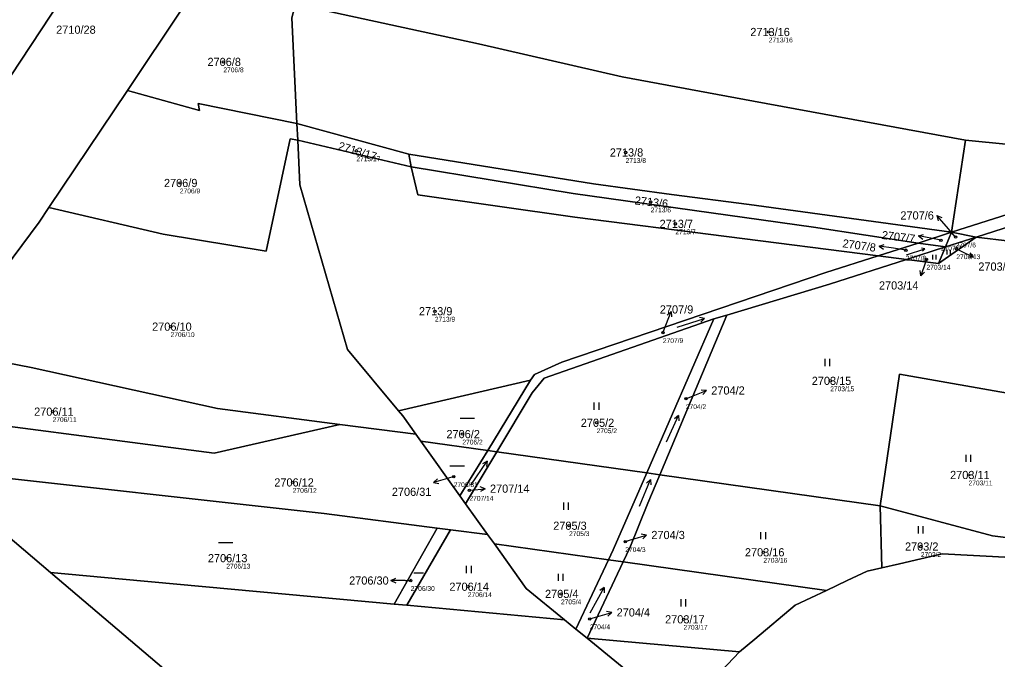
# Model space of a CAD drawing. Extents: x -739214 to -733252, y -1147612 to -1142842.
# Drawn here: x -738144.3 to -737941, y -1146269.3 to -1146136.2 of the extents above; entities that cross this region are included whole.
import ezdxf

# ---------------------------------------------------------------- set-up
doc = ezdxf.new("R2010")
doc.units = 0
for name, color, linetype in [('Definiční body', 7, 'Continuous'), ('Hranice parcel', 7, 'Continuous'), ('Parcelní čísla', 7, 'Continuous'), ('Polygon parcely', 7, 'Continuous'), ('Pop  PČ popisy', 7, 'Continuous'), ('Značky kultur', 7, 'Continuous')]:
    doc.layers.add(name, color=color, linetype=linetype)

msp = doc.modelspace()

# ---------------------------------------------------------------- linework, layer by layer
at = {"layer": 'Definiční body'}
for centre in [(-737988.53, -1146138.76), (-738101.92, -1146144.98), (-738074.27, -1146163.48), (-738018.28, -1146163.82), (-738110.96, -1146170.16), (-738013.08, -1146174.11), (-738007.93, -1146178.66), (-737952.75, -1146182.07), (-737949.69, -1146181.41), (-737960.03, -1146184.14), (-737949.52, -1146183.84), (-737955.74, -1146186.02), (-738057.95, -1146196.83), (-738112.89, -1146200.04), (-738010.54, -1146201.3), (-737975.75, -1146211.31), (-738005.76, -1146215.03), (-738137.42, -1146217.72), (-738024.31, -1146220.03), (-738052.23, -1146222.39), (-738054.03, -1146231.24), (-737946.99, -1146230.89), (-738087.49, -1146232.44), (-738050.76, -1146234.09), (-738030.04, -1146241.44), (-738018.36, -1146244.75), (-737956.91, -1146245.77), (-737989.65, -1146246.97), (-738101.3, -1146248.19), (-738062.96, -1146252.84), (-738051.09, -1146254.13), (-738031.73, -1146255.62), (-738025.74, -1146260.82), (-738006.24, -1146260.91)]:
    msp.add_circle(centre, 0.25, dxfattribs=at)
at = {"layer": 'Hranice parcel'}
for p, q in [((-738110.44, -1146133.83), (-738121.87, -1146150.92)), ((-738121.87, -1146150.92), (-738138.18, -1146175.28)), ((-738086.46, -1146161.25), (-738086.63, -1146157.8)), ((-738086.63, -1146157.8), (-738063.36, -1146164.2)), ((-738086.02, -1146170.57), (-738086.46, -1146161.25)), ((-738062.9, -1146166.81), (-738086.46, -1146161.25)), ((-737947.62, -1146161.29), (-737950.55, -1146180.42)), ((-737909.21, -1146165.1), (-737947.62, -1146161.29)), ((-738063.36, -1146164.2), (-738062.9, -1146166.81)), ((-738076.11, -1146204.78), (-738086.02, -1146170.57)), ((-737950.55, -1146180.42), (-737957.5, -1146182.65)), ((-737950.55, -1146180.42), (-737951.8, -1146183.47)), ((-737950.55, -1146180.42), (-737945.43, -1146181.43)), ((-737957.5, -1146182.65), (-737965.76, -1146185.31)), ((-737957.5, -1146182.65), (-737951.8, -1146183.47)), ((-737953.21, -1146186.91), (-737945.43, -1146181.43)), ((-737945.43, -1146181.43), (-737951.8, -1146183.47)), ((-737951.8, -1146183.47), (-737959.87, -1146186.06)), ((-737951.8, -1146183.47), (-737953.21, -1146186.91)), ((-737965.76, -1146185.31), (-737959.87, -1146186.06)), ((-737959.87, -1146186.06), (-737953.21, -1146186.91)), ((-737999.95, -1146198.39), (-738013.91, -1146230.45)), ((-738011.17, -1146230.84), (-737997.23, -1146197.63)), ((-737997.23, -1146197.63), (-737999.95, -1146198.39)), ((-738065.51, -1146217.55), (-738076.11, -1146204.78)), ((-738038.05, -1146211.17), (-738065.51, -1146217.55)), ((-738046.97, -1146225.8), (-738038.05, -1146211.17)), ((-738077.68, -1146220.38), (-738061.9, -1146222.43)), ((-738061.9, -1146222.43), (-738060.89, -1146223.85)), ((-738060.89, -1146223.85), (-738046.97, -1146225.8)), ((-738052.73, -1146235.25), (-738060.89, -1146223.85)), ((-738052.73, -1146235.25), (-738046.97, -1146225.8)), ((-738045.07, -1146226.07), (-738051.56, -1146236.89)), ((-738046.97, -1146225.8), (-738045.07, -1146226.07)), ((-738045.07, -1146226.07), (-738013.91, -1146230.45)), ((-738013.91, -1146230.45), (-738011.17, -1146230.84)), ((-738011.17, -1146230.84), (-737965.37, -1146237.28)), ((-738051.56, -1146236.89), (-738052.73, -1146235.25)), ((-738046.98, -1146243.28), (-738051.56, -1146236.89)), ((-737965.37, -1146237.28), (-737965, -1146250.2)), ((-738066.44, -1146257.74), (-738057.45, -1146241.93)), ((-738054.72, -1146242.29), (-738063.79, -1146257.98)), ((-738057.45, -1146241.93), (-738054.72, -1146242.29)), ((-738054.72, -1146242.29), (-738046.98, -1146243.28)), ((-738045.58, -1146245.23), (-738046.98, -1146243.28)), ((-738045.58, -1146245.23), (-738021.87, -1146248.55)), ((-738038.95, -1146254.51), (-738045.58, -1146245.23)), ((-738021.87, -1146248.55), (-738028.62, -1146262.95)), ((-738018.77, -1146248.98), (-738026.3, -1146264.85)), ((-738021.87, -1146248.55), (-738018.77, -1146248.98)), ((-738018.77, -1146248.98), (-737976.52, -1146254.9)), ((-737965, -1146250.2), (-737961.38, -1146249.36)), ((-737972.22, -1146252.87), (-737968.07, -1146250.91)), ((-737968.07, -1146250.91), (-737965, -1146250.2)), ((-737976.52, -1146254.9), (-737972.22, -1146252.87)), ((-738031.02, -1146260.99), (-738038.95, -1146254.51)), ((-737983.04, -1146257.99), (-737976.52, -1146254.9)), ((-738066.44, -1146257.74), (-738063.79, -1146257.98)), ((-738063.79, -1146257.98), (-738031.02, -1146260.99)), ((-738031.02, -1146260.99), (-738028.62, -1146262.95)), ((-738028.62, -1146262.95), (-738026.3, -1146264.85)), ((-738026.3, -1146264.85), (-737994.62, -1146267.7))]:
    msp.add_line(p, q, dxfattribs=at)
for points in [[(-738133.65, -1146128.9), (-738146.1, -1146147.9), (-738187.24, -1146201.43)], [(-738086.63, -1146157.8), (-738087.67, -1146135.8), (-738086.89, -1146132.94)], [(-737947.62, -1146161.29), (-737991.69, -1146153.16), (-738018.99, -1146148.09), (-738048.91, -1146141.19), (-738086.89, -1146132.94)], [(-738121.87, -1146150.92), (-738106.86, -1146155.08), (-738107.17, -1146153.63), (-738086.63, -1146157.8)], [(-738138.18, -1146175.28), (-738114.43, -1146180.81), (-738093.03, -1146184.32), (-738088.06, -1146160.96), (-738086.46, -1146161.25)], [(-737950.55, -1146180.42), (-737992.57, -1146174.67), (-738008.72, -1146172.55), (-738025, -1146170.34), (-738063.36, -1146164.2)], [(-737950.55, -1146180.42), (-737938.79, -1146176.64), (-737921.97, -1146170.82), (-737909.21, -1146165.1)], [(-738062.9, -1146166.81), (-738029.2, -1146172.33), (-737979.26, -1146179.33), (-737957.5, -1146182.65)], [(-738062.9, -1146166.81), (-738061.52, -1146172.64), (-738028.84, -1146177.24), (-737965.76, -1146185.31)], [(-737913.09, -1146169.9), (-737921.19, -1146173.66), (-737945.43, -1146181.43)], [(-738138.18, -1146175.28), (-738140.2, -1146178.3), (-738160.12, -1146204.97)], [(-737945.43, -1146181.43), (-737938.44, -1146182.28), (-737917.93, -1146184.94)], [(-737965.76, -1146185.31), (-737976.67, -1146188.81), (-738031.53, -1146207.43), (-738037.23, -1146209.99), (-738038.05, -1146211.17)], [(-737959.87, -1146186.06), (-737975.87, -1146191.19), (-737997.23, -1146197.63)], [(-737999.95, -1146198.39), (-738035.25, -1146210.77), (-738037.71, -1146213.81), (-738045.07, -1146226.07)], [(-738160.12, -1146204.97), (-738141.87, -1146208.53), (-738103.15, -1146217.07), (-738077.68, -1146220.38)], [(-737927.86, -1146215.8), (-737961.35, -1146209.95), (-737965.37, -1146237.28)], [(-738169.69, -1146217.79), (-738103.82, -1146226.35), (-738077.68, -1146220.38)], [(-738065.51, -1146217.55), (-738064.64, -1146218.6), (-738061.9, -1146222.43)], [(-738163.37, -1146229.62), (-738158.27, -1146230.29), (-738080.93, -1146238.92), (-738057.45, -1146241.93)], [(-738163.37, -1146229.62), (-738161.77, -1146230.87), (-738137.88, -1146251.17)], [(-738013.91, -1146230.45), (-738020.89, -1146246.47), (-738021.87, -1146248.55)], [(-738011.17, -1146230.84), (-738013.65, -1146236.75), (-738017.39, -1146246.07), (-738018.77, -1146248.98)], [(-737936.96, -1146244.2), (-737942.04, -1146243.53), (-737965.37, -1146237.28)], [(-737961.38, -1146249.36), (-737952.48, -1146247.3), (-737938.13, -1146248.08)], [(-738137.88, -1146251.17), (-738122.88, -1146252.56), (-738066.44, -1146257.74)], [(-738137.88, -1146251.17), (-738110.15, -1146274.73), (-738101.44, -1146281.71), (-738091.06, -1146290.01)], [(-737994.62, -1146267.7), (-737991.42, -1146265.02), (-737983.04, -1146257.99)], [(-737994.62, -1146267.7), (-738005.71, -1146279.42), (-738008.28, -1146279.57), (-738026.3, -1146264.85)]]:
    msp.add_lwpolyline(points, dxfattribs=at)
at = {"layer": 'Polygon parcely'}
for points in [[(-738071.28, -1146096.04), (-738082.64, -1146117.38), (-738086.89, -1146132.94), (-738048.91, -1146141.19), (-738018.99, -1146148.09), (-737991.69, -1146153.16), (-737947.62, -1146161.29), (-737909.21, -1146165.1), (-737907.13, -1146162.96), (-737889.89, -1146129.54), (-737952.88, -1146119.6), (-738034.62, -1146103.8)], [(-738205.06, -1146197.26), (-738187.24, -1146201.43), (-738146.1, -1146147.9), (-738133.65, -1146128.9), (-738131.34, -1146125.38), (-738147.44, -1146119.09), (-738158.29, -1146135.07), (-738163.2, -1146140.38), (-738171.83, -1146149.73), (-738181.3, -1146167.36), (-738188.43, -1146175.89), (-738195.24, -1146183.95), (-738201.39, -1146192.77)], [(-738187.24, -1146201.43), (-738193.9, -1146210.1), (-738201.84, -1146219.5), (-738199.97, -1146222.65), (-738198.89, -1146224.47), (-738196.13, -1146228.59), (-738179.3, -1146230.66), (-738173.26, -1146221.9), (-738169.69, -1146217.79), (-738160.12, -1146204.97), (-738140.2, -1146178.3), (-738138.18, -1146175.28), (-738121.87, -1146150.92), (-738110.44, -1146133.83), (-738126.38, -1146131.45), (-738133.65, -1146128.9), (-738146.1, -1146147.9)], [(-738107.17, -1146153.63), (-738086.63, -1146157.8), (-738087.67, -1146135.8), (-738086.89, -1146132.94), (-738107.97, -1146130.15), (-738110.44, -1146133.83), (-738121.87, -1146150.92), (-738106.86, -1146155.08)], [(-738018.99, -1146148.09), (-738048.91, -1146141.19), (-738086.89, -1146132.94), (-738087.67, -1146135.8), (-738086.63, -1146157.8), (-738063.36, -1146164.2), (-738025, -1146170.34), (-738008.72, -1146172.55), (-737992.57, -1146174.67), (-737950.55, -1146180.42), (-737947.62, -1146161.29), (-737991.69, -1146153.16)], [(-738088.06, -1146160.96), (-738086.46, -1146161.25), (-738086.63, -1146157.8), (-738107.17, -1146153.63), (-738106.86, -1146155.08), (-738121.87, -1146150.92), (-738138.18, -1146175.28), (-738114.43, -1146180.81), (-738093.03, -1146184.32)], [(-738086.63, -1146157.8), (-738086.46, -1146161.25), (-738062.9, -1146166.81), (-738063.36, -1146164.2)], [(-738086.02, -1146170.57), (-738086.46, -1146161.25), (-738088.06, -1146160.96), (-738093.03, -1146184.32), (-738114.43, -1146180.81), (-738138.18, -1146175.28), (-738140.2, -1146178.3), (-738160.12, -1146204.97), (-738141.87, -1146208.53), (-738103.15, -1146217.07), (-738077.68, -1146220.38), (-738061.9, -1146222.43), (-738064.64, -1146218.6), (-738065.51, -1146217.55), (-738076.11, -1146204.78)], [(-738062.9, -1146166.81), (-738086.46, -1146161.25), (-738086.02, -1146170.57), (-738076.11, -1146204.78), (-738065.51, -1146217.55), (-738038.05, -1146211.17), (-738037.23, -1146209.99), (-738031.53, -1146207.43), (-737976.67, -1146188.81), (-737965.76, -1146185.31), (-738028.84, -1146177.24), (-738061.52, -1146172.64)], [(-737950.55, -1146180.42), (-737938.79, -1146176.64), (-737921.97, -1146170.82), (-737909.21, -1146165.1), (-737947.62, -1146161.29)], [(-738063.36, -1146164.2), (-738062.9, -1146166.81), (-738029.2, -1146172.33), (-737979.26, -1146179.33), (-737957.5, -1146182.65), (-737950.55, -1146180.42), (-737992.57, -1146174.67), (-738008.72, -1146172.55), (-738025, -1146170.34)], [(-737950.55, -1146180.42), (-737945.43, -1146181.43), (-737921.19, -1146173.66), (-737913.09, -1146169.9), (-737910.33, -1146168.28), (-737907.35, -1146166.88), (-737906.08, -1146165.16), (-737909.21, -1146165.1), (-737921.97, -1146170.82), (-737938.79, -1146176.64)], [(-738061.52, -1146172.64), (-738028.84, -1146177.24), (-737965.76, -1146185.31), (-737957.5, -1146182.65), (-737979.26, -1146179.33), (-738029.2, -1146172.33), (-738062.9, -1146166.81)], [(-737945.43, -1146181.43), (-737938.44, -1146182.28), (-737917.93, -1146184.94), (-737913.09, -1146169.9), (-737921.19, -1146173.66)], [(-737957.5, -1146182.65), (-737951.8, -1146183.47), (-737950.55, -1146180.42)], [(-737950.55, -1146180.42), (-737951.8, -1146183.47), (-737945.43, -1146181.43)], [(-737997.23, -1146197.63), (-738011.17, -1146230.84), (-737965.37, -1146237.28), (-737961.35, -1146209.95), (-737927.86, -1146215.8), (-737917.93, -1146184.94), (-737938.44, -1146182.28), (-737945.43, -1146181.43), (-737953.21, -1146186.91), (-737959.87, -1146186.06), (-737975.87, -1146191.19)], [(-737965.76, -1146185.31), (-737959.87, -1146186.06), (-737951.8, -1146183.47), (-737957.5, -1146182.65)], [(-737945.43, -1146181.43), (-737951.8, -1146183.47), (-737953.21, -1146186.91)], [(-737959.87, -1146186.06), (-737953.21, -1146186.91), (-737951.8, -1146183.47)], [(-738031.53, -1146207.43), (-738037.23, -1146209.99), (-738038.05, -1146211.17), (-738046.97, -1146225.8), (-738045.07, -1146226.07), (-738037.71, -1146213.81), (-738035.25, -1146210.77), (-737999.95, -1146198.39), (-737997.23, -1146197.63), (-737975.87, -1146191.19), (-737959.87, -1146186.06), (-737965.76, -1146185.31), (-737976.67, -1146188.81)], [(-738037.71, -1146213.81), (-738045.07, -1146226.07), (-738013.91, -1146230.45), (-737999.95, -1146198.39), (-738035.25, -1146210.77)], [(-738013.91, -1146230.45), (-738011.17, -1146230.84), (-737997.23, -1146197.63), (-737999.95, -1146198.39)], [(-738160.12, -1146204.97), (-738169.69, -1146217.79), (-738103.82, -1146226.35), (-738077.68, -1146220.38), (-738103.15, -1146217.07), (-738141.87, -1146208.53)], [(-738060.89, -1146223.85), (-738046.97, -1146225.8), (-738038.05, -1146211.17), (-738065.51, -1146217.55), (-738064.64, -1146218.6), (-738061.9, -1146222.43)], [(-737965.37, -1146237.28), (-737942.04, -1146243.53), (-737936.96, -1146244.2), (-737936.45, -1146242.51), (-737927.86, -1146215.8), (-737961.35, -1146209.95)], [(-738046.98, -1146243.28), (-738051.56, -1146236.89), (-738052.73, -1146235.25), (-738060.89, -1146223.85), (-738061.9, -1146222.43), (-738077.68, -1146220.38), (-738103.82, -1146226.35), (-738169.69, -1146217.79), (-738173.26, -1146221.9), (-738172.94, -1146222.15), (-738163.37, -1146229.62), (-738158.27, -1146230.29), (-738080.93, -1146238.92), (-738057.45, -1146241.93), (-738054.72, -1146242.29)], [(-738099.06, -1146304.13), (-738091.06, -1146290.01), (-738101.44, -1146281.71), (-738110.15, -1146274.73), (-738137.88, -1146251.17), (-738161.77, -1146230.87), (-738163.37, -1146229.62), (-738172.94, -1146222.15), (-738173.26, -1146221.9), (-738179.3, -1146230.66), (-738187.36, -1146241.45), (-738173.43, -1146262.56), (-738160.45, -1146278.42), (-738140.73, -1146296.36), (-738128.52, -1146309.45), (-738121.57, -1146300.59), (-738103.8, -1146313.3)], [(-738052.73, -1146235.25), (-738046.97, -1146225.8), (-738060.89, -1146223.85)], [(-738052.73, -1146235.25), (-738051.56, -1146236.89), (-738045.07, -1146226.07), (-738046.97, -1146225.8)], [(-738021.87, -1146248.55), (-738020.89, -1146246.47), (-738013.91, -1146230.45), (-738045.07, -1146226.07), (-738051.56, -1146236.89), (-738046.98, -1146243.28), (-738045.58, -1146245.23)], [(-738066.44, -1146257.74), (-738057.45, -1146241.93), (-738080.93, -1146238.92), (-738158.27, -1146230.29), (-738163.37, -1146229.62), (-738161.77, -1146230.87), (-738137.88, -1146251.17), (-738122.88, -1146252.56)], [(-738020.89, -1146246.47), (-738021.87, -1146248.55), (-738018.77, -1146248.98), (-738017.39, -1146246.07), (-738013.65, -1146236.75), (-738011.17, -1146230.84), (-738013.91, -1146230.45)], [(-737968.07, -1146250.91), (-737965, -1146250.2), (-737965.37, -1146237.28), (-738011.17, -1146230.84), (-738013.65, -1146236.75), (-738017.39, -1146246.07), (-738018.77, -1146248.98), (-737976.52, -1146254.9), (-737972.22, -1146252.87)], [(-737965.37, -1146237.28), (-737965, -1146250.2), (-737961.38, -1146249.36), (-737952.48, -1146247.3), (-737938.13, -1146248.08), (-737936.96, -1146244.2), (-737942.04, -1146243.53)], [(-738066.44, -1146257.74), (-738063.79, -1146257.98), (-738054.72, -1146242.29), (-738057.45, -1146241.93)], [(-738054.72, -1146242.29), (-738063.79, -1146257.98), (-738031.02, -1146260.99), (-738038.95, -1146254.51), (-738045.58, -1146245.23), (-738046.98, -1146243.28)], [(-738028.62, -1146262.95), (-738021.87, -1146248.55), (-738045.58, -1146245.23), (-738038.95, -1146254.51), (-738031.02, -1146260.99)], [(-738021.87, -1146248.55), (-738028.62, -1146262.95), (-738026.3, -1146264.85), (-738018.77, -1146248.98)], [(-738026.3, -1146264.85), (-737994.62, -1146267.7), (-737991.42, -1146265.02), (-737983.04, -1146257.99), (-737976.52, -1146254.9), (-738018.77, -1146248.98)], [(-737994.62, -1146267.7), (-738026.3, -1146264.85), (-738008.28, -1146279.57), (-738005.71, -1146279.42)]]:
    msp.add_lwpolyline(points, close=True, dxfattribs=at)
for points in [[(-737900.94, -1146273.69), (-737910, -1146264.02), (-737912.72, -1146261.78), (-737916.48, -1146258.69), (-737921.7, -1146254.4), (-737935.36, -1146248.71), (-737936.68, -1146248.16), (-737938.13, -1146248.08), (-737952.48, -1146247.3), (-737961.38, -1146249.36), (-737965, -1146250.2), (-737968.07, -1146250.91), (-737972.22, -1146252.87), (-737976.52, -1146254.9), (-737983.04, -1146257.99), (-737991.42, -1146265.02), (-737994.62, -1146267.7), (-738005.71, -1146279.42)], [(-738008.28, -1146279.57), (-738026.3, -1146264.85), (-738028.62, -1146262.95), (-738031.02, -1146260.99), (-738063.79, -1146257.98), (-738066.44, -1146257.74), (-738122.88, -1146252.56), (-738137.88, -1146251.17), (-738110.15, -1146274.73)]]:
    msp.add_lwpolyline(points, dxfattribs=at)
at = {"layer": 'Pop  PČ popisy'}
for p, q in [((-737951.6, -1146179.19), (-737953.57, -1146176.93)), ((-737953.57, -1146176.93), (-737952.53, -1146177.35)), ((-737953.57, -1146176.93), (-737953.29, -1146178.01)), ((-737949.69, -1146181.41), (-737951.6, -1146179.19)), ((-737957.42, -1146181.17), (-737956.34, -1146180.87)), ((-737954.47, -1146181.74), (-737957.42, -1146181.17)), ((-737957.42, -1146181.17), (-737956.53, -1146181.85)), ((-737952.75, -1146182.07), (-737954.47, -1146181.74)), ((-737965.58, -1146183.27), (-737964.52, -1146182.93)), ((-737962.62, -1146183.74), (-737965.58, -1146183.27)), ((-737965.58, -1146183.27), (-737964.67, -1146183.92)), ((-737960.03, -1146184.14), (-737962.62, -1146183.74)), ((-737949.52, -1146183.84), (-737948.66, -1146184.25)), ((-737948.66, -1146184.25), (-737945.96, -1146185.57)), ((-737945.96, -1146185.57), (-737946.64, -1146184.68)), ((-737955.96, -1146186.65), (-737956.94, -1146189.49)), ((-737955.74, -1146186.02), (-737955.96, -1146186.65)), ((-737945.96, -1146185.57), (-737947.08, -1146185.58)), ((-737956.94, -1146189.49), (-737957.08, -1146188.38)), ((-737956.94, -1146189.49), (-737956.14, -1146188.7)), ((-738009.93, -1146199.7), (-738008.85, -1146196.9)), ((-738008.85, -1146196.9), (-738009.68, -1146197.65)), ((-738008.85, -1146196.9), (-738008.75, -1146198.01)), ((-738010.54, -1146201.3), (-738009.93, -1146199.7)), ((-738001.48, -1146213.31), (-738002.59, -1146213.22)), ((-738005.76, -1146215.03), (-738004.26, -1146214.43)), ((-738004.26, -1146214.43), (-738001.48, -1146213.31)), ((-738001.48, -1146213.31), (-738002.22, -1146214.15)), ((-738054.03, -1146231.24), (-738055.32, -1146231.6)), ((-738055.32, -1146231.6), (-738058.2, -1146232.43)), ((-738058.2, -1146232.43), (-738057.38, -1146231.67)), ((-738058.2, -1146232.43), (-738057.1, -1146232.63)), ((-738047.48, -1146233.75), (-738048.53, -1146233.35)), ((-738050.76, -1146234.09), (-738050.47, -1146234.06)), ((-738050.47, -1146234.06), (-738047.48, -1146233.75)), ((-738047.48, -1146233.75), (-738048.43, -1146234.35)), ((-738016.8, -1146244.26), (-738013.93, -1146243.38)), ((-738013.93, -1146243.38), (-738015.03, -1146243.2)), ((-738013.93, -1146243.38), (-738014.74, -1146244.15)), ((-738018.36, -1146244.75), (-738016.8, -1146244.26)), ((-738067.09, -1146252.84), (-738066.09, -1146252.34)), ((-738064.09, -1146252.84), (-738067.09, -1146252.84)), ((-738067.09, -1146252.84), (-738066.09, -1146253.34)), ((-738064.09, -1146252.84), (-738062.96, -1146252.84)), ((-738024.04, -1146260.32), (-738021.16, -1146259.49)), ((-738021.16, -1146259.49), (-738022.26, -1146259.29)), ((-738021.16, -1146259.49), (-738021.98, -1146260.25)), ((-738025.74, -1146260.82), (-738024.04, -1146260.32))]:
    msp.add_line(p, q, dxfattribs=at)
at = {"layer": 'Značky kultur'}
for p, q in [((-737959.9, -1146185.09), (-737956.08, -1146183.85)), ((-737956.08, -1146183.85), (-737956.8, -1146183.73)), ((-737956.08, -1146183.85), (-737956.59, -1146184.37)), ((-737951.42, -1146185.07), (-737951.42, -1146184.06)), ((-737950.75, -1146185.07), (-737950.75, -1146184.06)), ((-737954.4, -1146186.1), (-737954.4, -1146185.09)), ((-737953.73, -1146186.1), (-737953.73, -1146185.09)), ((-738007.57, -1146200.17), (-738001.87, -1146198.32)), ((-738001.87, -1146198.32), (-738002.95, -1146198.14)), ((-738001.87, -1146198.32), (-738002.64, -1146199.09)), ((-737976.8, -1146208.24), (-737976.8, -1146206.74)), ((-737975.8, -1146208.24), (-737975.8, -1146206.74)), ((-738024.82, -1146217.33), (-738024.82, -1146215.83)), ((-738023.82, -1146217.33), (-738023.82, -1146215.83)), ((-738052.68, -1146219.04), (-738049.68, -1146219.04)), ((-738009.81, -1146223.97), (-738007.28, -1146218.53)), ((-738007.28, -1146218.53), (-738008.15, -1146219.2)), ((-738007.28, -1146218.53), (-738007.24, -1146219.63)), ((-737947.5, -1146228.19), (-737947.5, -1146226.69)), ((-737946.5, -1146228.19), (-737946.5, -1146226.69)), ((-738054.81, -1146228.99), (-738051.81, -1146228.99)), ((-738050.44, -1146233), (-738047.09, -1146228.02)), ((-738047.09, -1146228.02), (-738048.05, -1146228.55)), ((-738047.09, -1146228.02), (-738047.22, -1146229.11)), ((-738015.37, -1146237.41), (-738013.12, -1146231.85)), ((-738013.12, -1146231.85), (-738013.95, -1146232.56)), ((-738013.12, -1146231.85), (-738013.02, -1146232.94)), ((-738031.14, -1146238.13), (-738031.14, -1146236.63)), ((-738030.14, -1146238.13), (-738030.14, -1146236.63)), ((-737957.42, -1146243.07), (-737957.42, -1146241.57)), ((-737956.42, -1146243.07), (-737956.42, -1146241.57)), ((-737990.16, -1146244.27), (-737990.16, -1146242.77)), ((-737989.16, -1146244.27), (-737989.16, -1146242.77)), ((-738102.93, -1146244.96), (-738099.93, -1146244.96)), ((-738051.34, -1146251.29), (-738051.34, -1146249.79)), ((-738050.34, -1146251.29), (-738050.34, -1146249.79)), ((-738062.31, -1146251.25), (-738060.3, -1146251.25)), ((-738032.24, -1146252.92), (-738032.24, -1146251.42)), ((-738031.24, -1146252.92), (-738031.24, -1146251.42)), ((-738025.63, -1146259.53), (-738022.72, -1146254.28)), ((-738022.72, -1146254.28), (-738023.63, -1146254.9)), ((-738022.72, -1146254.28), (-738022.76, -1146255.38)), ((-738006.75, -1146258.21), (-738006.75, -1146256.71)), ((-738005.75, -1146258.21), (-738005.75, -1146256.71))]:
    msp.add_line(p, q, dxfattribs=at)

# ---------------------------------------------------------------- texts
at = {"layer": 'Definiční body'}
for s, p in [('2713/16', (-737988.53, -1146140.92)), ('2706/8', (-738101.92, -1146147.14)), ('2713/17', (-738074.27, -1146165.64)), ('2713/8', (-738018.28, -1146165.98)), ('2706/9', (-738110.96, -1146172.32)), ('2713/6', (-738013.08, -1146176.27)), ('2713/7', (-738007.93, -1146180.82)), ('2707/6', (-737949.69, -1146183.57)), ('2707/7', (-737952.75, -1146184.23)), ('2707/8', (-737960.03, -1146186.3)), ('2703/13', (-737949.52, -1146186)), ('2703/14', (-737955.74, -1146188.18)), ('2713/9', (-738057.95, -1146198.99)), ('2706/10', (-738112.89, -1146202.2)), ('2707/9', (-738010.54, -1146203.46)), ('2703/15', (-737975.75, -1146213.47)), ('2704/2', (-738005.76, -1146217.19)), ('2706/11', (-738137.42, -1146219.88)), ('2705/2', (-738024.31, -1146222.19)), ('2706/2', (-738052.23, -1146224.55)), ('2706/12', (-738087.49, -1146234.6)), ('2706/31', (-738054.03, -1146233.4)), ('2703/11', (-737946.99, -1146233.05)), ('2707/14', (-738050.76, -1146236.25)), ('2705/3', (-738030.04, -1146243.6)), ('2704/3', (-738018.36, -1146246.91)), ('2703/2', (-737956.91, -1146247.93)), ('2706/13', (-738101.3, -1146250.35)), ('2703/16', (-737989.65, -1146249.13)), ('2706/30', (-738062.96, -1146255)), ('2706/14', (-738051.09, -1146256.29)), ('2705/4', (-738031.73, -1146257.78)), ('2704/4', (-738025.74, -1146262.98)), ('2703/17', (-738006.24, -1146263.07))]:
    msp.add_text(s, height=1, dxfattribs=at).set_placement(p)
at = {"layer": 'Parcelní čísla'}
for s, p in [('2710/28', (-738136.68, -1146139.13)), ('2713/16', (-737992.37, -1146139.61)), ('2706/8', (-738105.22, -1146145.83)), ('2713/8', (-738021.58, -1146164.67)), ('2706/9', (-738114.27, -1146171.01)), ('2707/6', (-737961.16, -1146177.76)), ('2713/7', (-738011.23, -1146179.51)), ('2703/13', (-737944.96, -1146188.39)), ('2703/14', (-737965.62, -1146192.32)), ('2713/9', (-738061.26, -1146197.68)), ('2707/9', (-738011.18, -1146197.31)), ('2706/10', (-738116.73, -1146200.89)), ('2703/15', (-737979.59, -1146212.16)), ('2704/2', (-738000.48, -1146214.16)), ('2706/11', (-738141.26, -1146218.57)), ('2705/2', (-738027.61, -1146220.88)), ('2706/2', (-738055.54, -1146223.24)), ('2706/12', (-738091.33, -1146233.29)), ('2703/11', (-737950.83, -1146231.74)), ('2706/31', (-738066.89, -1146235.24)), ('2707/14', (-738046.49, -1146234.58)), ('2705/3', (-738033.34, -1146242.29)), ('2704/3', (-738012.94, -1146244.22)), ('2703/2', (-737960.21, -1146246.62)), ('2706/13', (-738105.14, -1146249.04)), ('2703/16', (-737993.49, -1146247.82)), ('2706/30', (-738075.77, -1146253.69)), ('2706/14', (-738054.93, -1146254.98)), ('2705/4', (-738035.04, -1146256.47)), ('2704/4', (-738020.16, -1146260.32)), ('2703/17', (-738010.08, -1146261.76))]:
    msp.add_text(s, height=1.7, dxfattribs=at).set_placement(p)
for s, rotation, p in [('2713/17', 343, (-738078.19, -1146163.17)), ('2713/6', 354, (-738016.46, -1146174.61)), ('2707/7', 353, (-737965.11, -1146181.79)), ('2707/8', 352, (-737973.28, -1146183.51))]:
    msp.add_text(s, height=1.7, rotation=rotation, dxfattribs=at).set_placement(p)

doc.saveas('drawing.dxf')
